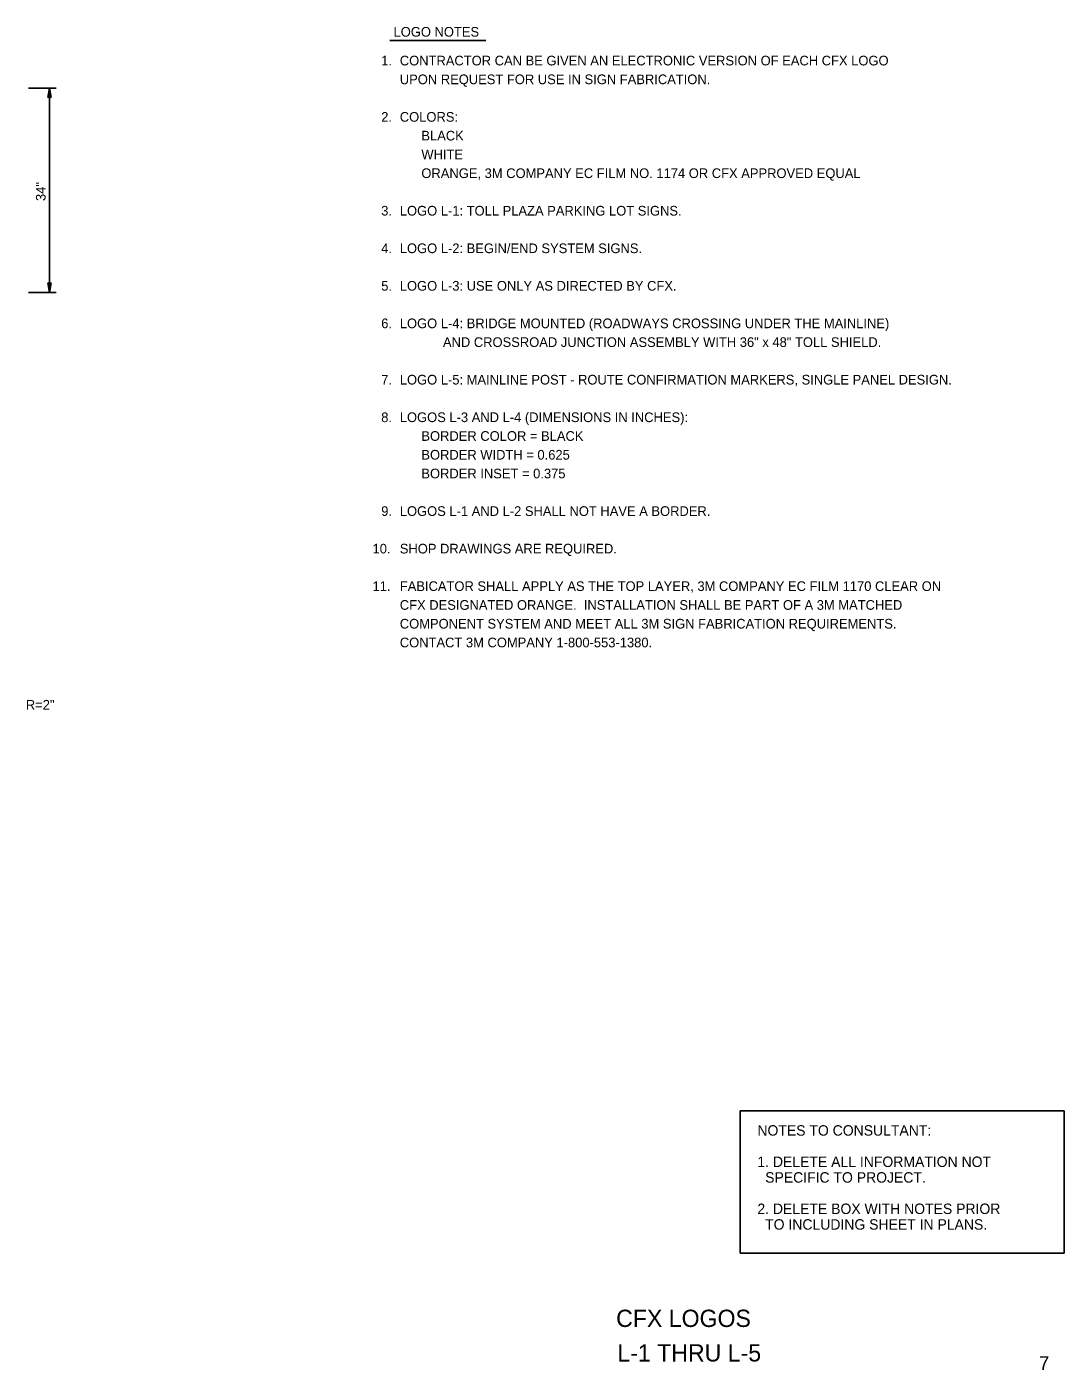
# Model space of a CAD drawing. Extents: x 60714 to 61343, y 7599 to 7998.
# Drawn here: x 61043.1 to 61343.3, y 7609.2 to 7998 of the extents above; entities that cross this region are included whole.
import ezdxf

# ---------------------------------------------------------------- set-up
doc = ezdxf.new("R2010")
doc.units = 0
for name, color, linetype in [('2', 7, 'Continuous'), ('21', 7, 'Continuous'), ('TextAlert', 7, 'Continuous'), ('TextMisc', 7, 'Continuous'), ('TextShtNo', 7, 'Continuous')]:
    doc.layers.add(name, color=color, linetype=linetype)

msp = doc.modelspace()

# ---------------------------------------------------------------- linework, layer by layer
at = {"layer": '2'}
for p, q in [((61148.08, 7993.97), (61175.94, 7993.97)), ((61043.58, 7980.26), (61051.58, 7980.26)), ((61049.58, 7921.12), (61049.58, 7980.26)), ((61043.58, 7921.12), (61051.58, 7921.12))]:
    msp.add_line(p, q, dxfattribs=at)
at = {"layer": '21'}
for p, q in [((61049.58, 7980.26), (61049.09, 7977.49)), ((61049.58, 7980.26), (61049.35, 7977.6)), ((61049.58, 7980.26), (61050.07, 7977.49)), ((61049.58, 7980.26), (61049.81, 7977.6)), ((61049.09, 7977.49), (61049.58, 7977.7)), ((61049.58, 7977.7), (61050.07, 7977.49)), ((61049.58, 7921.12), (61049.09, 7923.89)), ((61049.58, 7923.68), (61049.09, 7923.89)), ((61049.58, 7921.12), (61049.35, 7923.77)), ((61049.58, 7921.12), (61050.07, 7923.89)), ((61050.07, 7923.89), (61049.58, 7923.68)), ((61049.58, 7921.12), (61049.81, 7923.78))]:
    msp.add_line(p, q, dxfattribs=at)
at = {"layer": 'TextAlert'}
msp.add_lwpolyline([(61249.54, 7684.21), (61343.29, 7684.21), (61343.29, 7643.04), (61249.54, 7643.04)], close=True, dxfattribs=at)

# ---------------------------------------------------------------- texts
at = {"layer": '2'}
for s, p in [('LOGO NOTES', (61149.2, 7995.12)), ('R=2"', (61042.76, 7800.35))]:
    msp.add_text(s, height=2.8, dxfattribs=at).set_placement(p)
msp.add_text('34"', height=2.8, rotation=90, dxfattribs=at).set_placement((61048.49, 7947.55))
at = {"layer": '21'}
for s, p in [('1.', (61145.63, 7986.8)), ('CONTRACTOR CAN BE GIVEN AN ELECTRONIC VERSION OF EACH CFX LOGO', (61151.01, 7986.8)), ('UPON REQUEST FOR USE IN SIGN FABRICATION.', (61151.01, 7981.37)), ('2.', (61145.63, 7970.5)), ('COLORS:', (61151.01, 7970.5)), ('      BLACK', (61151.01, 7965.07)), ('      WHITE', (61151.01, 7959.64)), ('      ORANGE, 3M COMPANY EC FILM NO. 1174 OR CFX APPROVED EQUAL', (61151.01, 7954.2)), ('3.', (61145.63, 7943.34)), ('LOGO L-1: TOLL PLAZA PARKING LOT SIGNS.', (61151.01, 7943.34)), ('4.', (61145.63, 7932.47)), ('LOGO L-2: BEGIN/END SYSTEM SIGNS.', (61151.01, 7932.47)), ('5.', (61145.63, 7921.6)), ('LOGO L-3: USE ONLY AS DIRECTED BY CFX.', (61151.01, 7921.61)), ('6.', (61145.63, 7910.74)), ('LOGO L-4: BRIDGE MOUNTED (ROADWAYS CROSSING UNDER THE MAINLINE)', (61151.01, 7910.74)), ('            AND CROSSROAD JUNCTION ASSEMBLY WITH 36" x 48" TOLL SHIELD.', (61151.01, 7905.31)), ('7.', (61145.63, 7894.44)), ('LOGO L-5: MAINLINE POST - ROUTE CONFIRMATION MARKERS, SINGLE PANEL DESIGN.', (61151.01, 7894.44)), ('8.', (61145.63, 7883.57)), ('LOGOS L-3 AND L-4 (DIMENSIONS IN INCHES):', (61151.01, 7883.57)), ('      BORDER COLOR = BLACK', (61151.01, 7878.14)), ('      BORDER WIDTH = 0.625', (61151.01, 7872.71)), ('      BORDER INSET = 0.375', (61151.01, 7867.28)), ('9. ', (61145.63, 7856.41)), ('LOGOS L-1 AND L-2 SHALL NOT HAVE A BORDER.', (61151.01, 7856.41)), ('10.', (61143.12, 7845.54)), ('SHOP DRAWINGS ARE REQUIRED.', (61151.01, 7845.54)), ('11.', (61143.12, 7834.68)), ('FABICATOR SHALL APPLY AS THE TOP LAYER, 3M COMPANY EC FILM 1170 CLEAR ON ', (61151.01, 7834.68)), ('CFX DESIGNATED ORANGE.  INSTALLATION SHALL BE PART OF A 3M MATCHED ', (61151.01, 7829.24)), ('COMPONENT SYSTEM AND MEET ALL 3M SIGN FABRICATION REQUIREMENTS.  ', (61151.01, 7823.81)), ('CONTACT 3M COMPANY 1-800-553-1380.', (61151.01, 7818.38))]:
    msp.add_text(s, height=2.8, dxfattribs=at).set_placement(p)
at = {"layer": 'TextAlert'}
for s, p in [('NOTES TO CONSULTANT:', (61254.51, 7677.04)), ('1. DELETE ALL INFORMATION NOT', (61254.51, 7667.97)), ('  SPECIFIC TO PROJECT.', (61254.51, 7663.44)), ('2. DELETE BOX WITH NOTES PRIOR', (61254.51, 7654.36)), ('  TO INCLUDING SHEET IN PLANS.', (61254.51, 7649.83))]:
    msp.add_text(s, height=3.024, dxfattribs=at).set_placement(p)
at = {"layer": 'TextMisc'}
for s, p in [('       CFX LOGOS        ', (61200.62, 7621.67)), ('      L-1 THRU L-5      ', (61202.83, 7611.67))]:
    msp.add_text(s, height=5, rotation=360, dxfattribs=at).set_placement(p)
at = {"layer": 'TextShtNo'}
msp.add_text('7', height=4, rotation=360, dxfattribs=at).set_placement((61336, 7609.17))

doc.saveas('drawing.dxf')
